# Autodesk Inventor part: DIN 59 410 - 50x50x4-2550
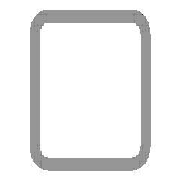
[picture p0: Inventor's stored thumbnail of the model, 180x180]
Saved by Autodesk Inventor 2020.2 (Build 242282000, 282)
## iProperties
Manager: www.cadconsulting.pl
Company: Fabian Stasiak CAD Consulting
IsCustomPart: 1
_CCFamilyMember: 40
_CCFamilyDisplayName: DIN 59410 (Kwadrat) - Rurki stalowe o przekroju kwadratowym formowane na gorąco
_FrameMemberDoc: Frame Member File
_Version: 15.0.0
_GetPNFromCC: 1
Created: 2015-01
Part Number: DIN 59 410 - 50x50x4-2550
Material: Stal, miękka
Description: Rurki stalowe o przekroju kwadratowym formowane na gorąco
Document SubType Name: Modellieren
Standard: DIN
Designer: F.Stasiak
Standards Organization: DIN
Language: pl-PL
Size Designation: 50x50x4
Categories: <MemberInstance><Categories><Category DisplayName="Kształtowniki konstrukcyjne" InternalName="089c4875-fa83-4c05-b084-43b9cc11f5ed" Mnemonic="GRDR"><CategoryPar
Stock Number: 50x50x4
Density: 7.85 g/cm^3
Appearance: Częściowo polerowana
Mass: 13635.4 g
Surface Area: 8704.61 cm^2
Volume: 1736.99 cm^3
Catalog Web Link: www.expertbooks.pl
G_L: 2550,000 mm
G_W: 50,000 mm
G_H: 50,000 mm
+86EC1A40-C4FA-4EDA-98C8-ADE4557E471B+CUTDETAIL1: Połączenie narożnikowe 45,00 deg
+B6354725-C38D-4B68-BB5C-FC2418608E11+CUTDETAIL2: Połączenie narożnikowe 45,00 deg
Author: F.Stasiak
Subject: Zbiór ćwiczeń. Autodesk Inventor 2020. Kurs Professional
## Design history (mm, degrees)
node "Płaszczyzna początkowa"
node "Płaszczyzna końcowa"
sketch "Szkic1"
  geometry: L1 (-17, 25)-(17, 25); L2 (25, 17)-(25, -17); L3 (17, -25)-(-17, -25); L4 (-25, -17)-(-25, 17); L5 (-36.682, 0)-(36.682, 0) reference; L6 (0, -36.682)-(0, 36.682) reference; L7 (-17, 21)-(17, 21); L8 (21, 17)-(21, -17); L9 (17, -21)-(-17, -21); L10 (-21, -17)-(-21, 17); A1 r 8 centre (-17, 17) between (-17, 25) and (-25, 17); A2 r 8 centre (17, 17) between (25, 17) and (17, 25); A3 r 8 centre (17, -17) between (17, -25) and (25, -17); A4 r 8 centre (-17, -17) between (-25, -17) and (-17, -25); A5 r 4 centre (-17, 17) between (-17, 21) and (-21, 17); A6 r 4 centre (17, 17) between (21, 17) and (17, 21); A7 r 4 centre (17, -17) between (17, -21) and (21, -17); A8 r 4 centre (-17, -17) between (-21, -17) and (-17, -21); 3 further points
  constraints: 16 end point, 16 point on circle, 8 centre point, 8 tangent, 6 point on line, 4 parallel, 3 equal radius, 3 perpendicular, 1 horizontal, 7 other
  dimensions: "b" = 50 distance of point (-25, 25) point (25, 25); "msp_r" = 8 radius of A1 (= 2 x ParT); "d8" = 25 distance between parallel lines of L4 L6 (= d9); "d9" = 25 distance between parallel lines of L3 L5 (= 0.5 x b); "d10" = 4 distance between parallel lines of L3 L9 (= ParT)
extrude "Bryła" new body sketch "Szkic1" taper "d4" = 0 deg; stored distance "NLG" = 10
node "Driven Length"
  sketch "Sketch2"
    geometry: L1 (0, 0)-(10, 0) reference
    constraints: 2 end point, 1 horizontal
  workplane "Work Plane3"
  sketch "Sketch3"
    geometry: L1 (-2, -25)-(12, -25) reference; L2 (-2, 2525)-(12, 2525) reference
    dimensions: "d14" = 2550 distance between parallel lines of L1 L2 (derived)
node "Płaszczyzna konstrukcyjna4"
feature "Podział1"
node "Płaszczyzna konstrukcyjna5"
feature "Podział2"
body "Solid1"
other parameters: "ParT" = 4, "G_OFFSET_START" = 25 [user parameter; used in 1 equation term], "G_OFFSET_END" = 25 [user parameter; used in 1 equation term], "d11" = -25 (= -G_OFFSET_START), "d12" = 2525 (= G_OFFSET_END + B_L), "G_L" = 2550 (= d14) [user parameter], "d13" = 90 deg
